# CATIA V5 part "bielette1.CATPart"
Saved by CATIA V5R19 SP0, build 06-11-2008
Part number: bielette1
Bounding box of the stored display mesh (mm): x -20 to 20, y 390 to 600, z -45 to 45
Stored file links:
  C:\Users\Thibaud\Desktop\IFMA\thinkmotion\IAO\modele_catia\bielette1.CATPart
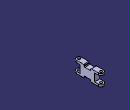
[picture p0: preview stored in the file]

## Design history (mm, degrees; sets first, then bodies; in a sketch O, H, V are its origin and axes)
Body1 (main body)
  Plane1: stored without definition
  Line1 "axe_pivot_bielette1_(bielette2_bielette3)": stored without definition
  Line2 "axe_pivot_bielette1_levier": stored without definition
  Line3: stored without definition
  Sketch1 on Plane1, origin (0, 0, 0), H (1, 0, 0), V (0, 1, 0)
    line L1 (-20, 440) -> (20, 440)
    line L2 (20, 440) -> (20, 550)
    line L3 (20, 550) -> (-20, 550)
    line L4 (-20, 550) -> (-20, 440)
    reference projected point E1 (0, 410) from Line1
    reference projected point E2 (0, 580) from Line2
    reference projected line E3 (0, 580) -> (0, 410) from Line3
    distance L1 E1 = 30
    distance E2 L3 = 30
    length L1 = 40
    distance L2 E3 = 20 {= Sketch1.length(L1) /2}
    horizontal: L1 H, L3 H
    vertical: L2 V, L4 V
  Pad1: profile Sketch1, direction (0, 0, 1), length 30, mirrored extent
  Line4 "axe_pivot_bielette1_(bielette2_bielette3)": stored without definition
  Line5 "axe_pivot_bielette1_(bielette2_bielette3)": stored without definition
  Plane2: stored without definition
  Sketch2 on end face of Pad1, origin (0, 0, 30), H (1, 0, 0), V (0, 1, 0)
    point P1 (-20, 470)
    line L1 (-20, 470) -> (-20, 410)
    point P2 (-20, 410)
    arc A1 centre (0, 410) radius 20 from (-20, 410) to (20, 410) ccw
    point P3 (0, 410)
    point P4 (20, 410)
    line L2 (20, 410) -> (20, 470)
    point P5 (20, 470)
    line L3 (20, 470) -> (-20, 470)
    reference projected line E1 (20, 440) -> (20, 550) from edge [face of Pad1 from Sketch1.L2 | end face of Pad1]
    reference projected line E2 (-20, 550) -> (-20, 440) from edge [face of Pad1 from Sketch1.L4 | end face of Pad1]
    reference projected point E3 (0, 410) from Line4
    axis line L4 (-65.7294, 495) -> (58.1985, 495)
    reference projected point E4 (0, 410) from Line1
    reference projected line E5 (-20, 440) -> (20, 440) from edge [face of Pad1 from Sketch1.L1 | end face of Pad1]
    circle A2 centre (0, 410) radius 10
    point P8 (0, 410)
    reference projected point E6 (0, 410) from Line6
    point P9 (20, 580)
    point P10 (-20, 580)
    arc A3 centre (0, 580) radius 20 from (-20, 580) to (20, 580) cw
    circle A4 centre (0, 580) radius 10
    point P13 (-20, 520)
    line L5 (-20, 520) -> (-20, 580)
    point P14 (20, 520)
    line L6 (20, 520) -> (-20, 520)
    line L7 (20, 580) -> (20, 520)
    distance E4 L4 = 85
    distance E5 L3 = 30
    radius A2 = 10
    vertical: L1 V
    tangency: A1 L1, L2 A1
    horizontal: L3 H, L4 H
    coincidence: L2 E1, L1 E2, P3 E3, P8 E6
    symmetry: P4 P9 L4, P2 P10 L4, A1 A3 L4, A2 A4 L4, P1 P13 L4, L1 L5 L4, P5 P14 L4, L3 L6 L4, L2 L7 L4
  Pad2: profile Sketch2, direction (0, 0, 1), length 15
  Mirror1: of Pad2, about Plane2
  Fillet1: radius 5, on edge [end face of Pad1 | face of Pad2 from Sketch2.L3]; edge [face of Pad2 from Sketch2.L3 | end face of Pad2]; edge [face of Pad2 from Sketch2.L6 | end face of Pad2]; edge [end face of Pad1 | face of Pad2 from Sketch2.L6]; edge [face of Mirror1 | start face of Pad1] (x2); edge [face of Mirror1 | face of Mirror1] (x2)
  Line6 "axe_pivot_bielette1_(bielette2_bielette3)": stored without definition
